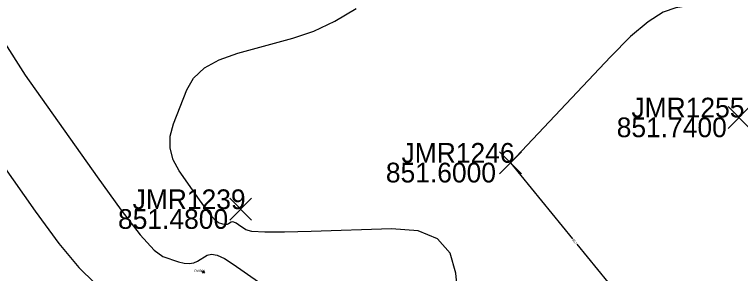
# Model space of a CAD drawing. Extents: x 1654928 to 1810050, y 486881 to 626330.
# Drawn here: x 1801514.13 to 1801558.26, y 489860.85 to 489876.6 of the extents above; entities that cross this region are included whole.
import ezdxf

# ---------------------------------------------------------------- set-up
doc = ezdxf.new("R2010")
doc.units = 0
for name, color, linetype in [('DT_X_Contour_Major', 7, 'Continuous'), ('DT_X_Contour_Minor', 7, 'Continuous'), ('GK_Visualization', 7, 'Continuous'), ('SV_X_Random_Point', 7, 'Continuous'), ('SV_X_Text_Elevation', 7, 'Continuous'), ('SV_X_Text_Name', 7, 'Continuous')]:
    doc.layers.add(name, color=color, linetype=linetype)

msp = doc.modelspace()

# ---------------------------------------------------------------- linework, layer by layer
at = {"layer": 'DT_X_Contour_Major'}
msp.add_lwpolyline([(1801511.202, 489870.559), (1801515.376, 489864.638), (1801516.824, 489862.67), (1801518.035, 489861.209), (1801519.01, 489860.254)], dxfattribs=at)
at = {"layer": 'DT_X_Contour_Minor'}
for points in [[(1801557.568, 489877.534), (1801554.333, 489877.017), (1801553.563, 489876.748), (1801552.643, 489876.16), (1801551.57, 489875.256), (1801550.346, 489874.033), (1801544.278, 489867.587), (1801548.045, 489862.957)], [(1801541.314, 489857.108), (1801540.959, 489860.864), (1801540.614, 489862.089), (1801539.846, 489862.946), (1801538.654, 489863.436), (1801537.039, 489863.558), (1801532.167, 489863.394), (1801530.548, 489863.355), (1801529.344, 489863.359), (1801528.557, 489863.408), (1801528.184, 489863.502), (1801527.746, 489863.809), (1801527.595, 489863.905), (1801527.469, 489863.963), (1801527.368, 489863.982), (1801527.293, 489863.963), (1801527.127, 489863.861), (1801527.06, 489863.832), (1801526.982, 489863.82), (1801526.894, 489863.826), (1801526.796, 489863.85), (1801526.52, 489863.937), (1801526.371, 489864.048), (1801526.131, 489864.317), (1801525.801, 489864.743), (1801525.379, 489865.326), (1801524.134, 489867.092), (1801523.763, 489867.768), (1801523.583, 489868.472), (1801523.595, 489869.203), (1801523.798, 489869.961), (1801524.594, 489872.02), (1801525.013, 489872.739), (1801525.67, 489873.35), (1801526.567, 489873.853), (1801527.703, 489874.25), (1801531.052, 489875.163), (1801532.317, 489875.593), (1801533.599, 489876.195), (1801534.9, 489876.971)], [(1801513.407, 489875.078), (1801514.785, 489872.916), (1801519.142, 489866.735), (1801520.617, 489864.693), (1801521.774, 489863.201), (1801522.613, 489862.261), (1801523.134, 489861.871), (1801524.099, 489861.566), (1801524.443, 489861.483), (1801524.751, 489861.462), (1801525.023, 489861.503), (1801525.259, 489861.606), (1801525.84, 489861.963), (1801526.102, 489862.03), (1801526.454, 489861.962), (1801526.896, 489861.76), (1801527.426, 489861.424), (1801528.96, 489860.348)], [(1801548.311, 489862.632), (1801550.187, 489860.326), (1801551.415, 489859.003), (1801552.567, 489858.145), (1801553.643, 489857.752), (1801554.643, 489857.825), (1801557.207, 489858.638), (1801558.05, 489858.907), (1801558.656, 489859.104), (1801559.025, 489859.229), (1801559.156, 489859.282), (1801559.191, 489859.326), (1801559.206, 489859.16), (1801559.225, 489858.631), (1801559.248, 489857.739), (1801559.276, 489856.483), (1801559.415, 489849.772)]]:
    msp.add_lwpolyline(points, dxfattribs=at)
at = {"layer": 'GK_Visualization'}
for p, q in [((1801525.546, 489860.868), (1801525.679, 489861.001)), ((1801525.546, 489861.001), (1801525.679, 489860.868))]:
    msp.add_line(p, q, dxfattribs=at)
at = {"layer": 'SV_X_Random_Point'}
for p, q in [((1801557.5, 489869.672), (1801558.833, 489871.007)), ((1801557.5, 489871.007), (1801558.833, 489869.672)), ((1801543.611, 489866.919), (1801544.945, 489868.254)), ((1801543.611, 489868.254), (1801544.945, 489866.919)), ((1801527.208, 489864.096), (1801528.541, 489865.431)), ((1801527.208, 489865.431), (1801528.541, 489864.096))]:
    msp.add_line(p, q, dxfattribs=at)

# ---------------------------------------------------------------- texts
at = {"layer": 'DT_X_Contour_Minor'}
msp.add_text('852', height=0.14, rotation=309.1393, dxfattribs=at).set_placement((1801548.023, 489862.873))
at = {"layer": 'GK_Visualization'}
msp.add_text('RW301', height=0.14, dxfattribs=at).set_placement((1801525.061, 489860.934))
at = {"layer": 'SV_X_Text_Elevation'}
for s, p in [('851.7400', (1801550.732, 489869.14)), ('851.6000', (1801536.701, 489866.387)), ('851.4800', (1801520.42, 489863.563))]:
    msp.add_text(s, height=1.2, dxfattribs=at).set_placement(p)
at = {"layer": 'SV_X_Text_Name'}
for s, p in [('JMR1255', (1801551.629, 489870.34)), ('JMR1246', (1801537.655, 489867.587)), ('JMR1239', (1801521.308, 489864.763))]:
    msp.add_text(s, height=1.2, dxfattribs=at).set_placement(p)

doc.saveas('drawing.dxf')
